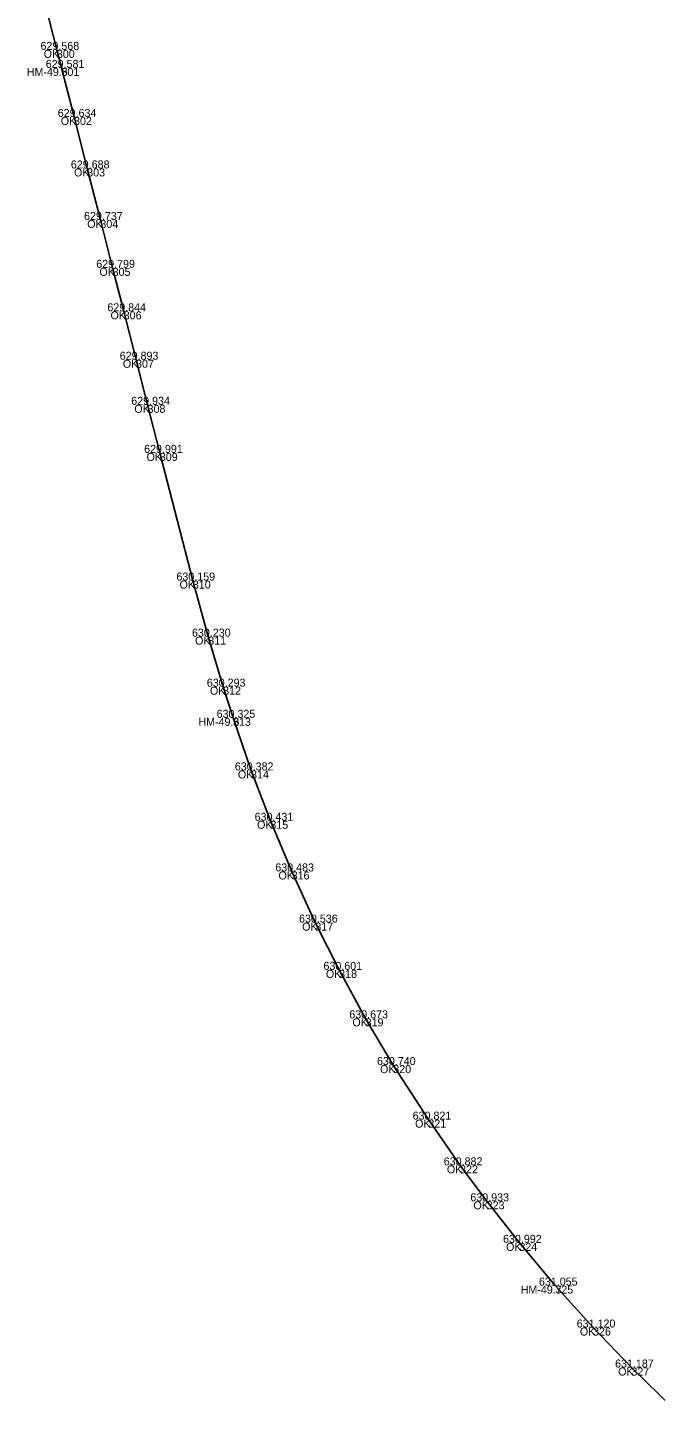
# Model space of a CAD drawing. Extents: x -631472 to -620808, y -1122356 to -1115125.
# Drawn here: x -629565.6 to -629471.4, y -1115712.2 to -1115505.1 of the extents above; entities that cross this region are included whole.
import ezdxf

# ---------------------------------------------------------------- set-up
doc = ezdxf.new("R2010")
doc.units = 0
for name, color, linetype in [('Vrstva 1', 7, 'Continuous'), ('Vrstva 60', 7, 'Continuous'), ('Vrstva 61', 7, 'Continuous'), ('Vrstva 62', 7, 'Continuous')]:
    doc.layers.add(name, color=color, linetype=linetype)

msp = doc.modelspace()

# ---------------------------------------------------------------- linework, layer by layer
at = {"layer": 'Vrstva 1'}
msp.add_lwpolyline([(-629562.87, -1115501.74), (-629561.17, -1115508.42), (-629560.48, -1115511.12), (-629558.59, -1115518.48), (-629556.62, -1115526.2), (-629554.64, -1115533.93), (-629552.8, -1115541.11), (-629551.14, -1115547.63), (-629549.29, -1115554.89), (-629547.56, -1115561.65), (-629545.72, -1115568.86), (-629540.77, -1115588.01), (-629538.45, -1115596.42), (-629536.22, -1115603.92), (-629534.74, -1115608.59), (-629532.03, -1115616.48), (-629529.14, -1115624.03), (-629525.94, -1115631.63), (-629522.39, -1115639.3), (-629518.81, -1115646.39), (-629514.84, -1115653.66), (-629510.69, -1115660.67), (-629505.43, -1115668.85), (-629500.67, -1115675.71), (-629496.68, -1115681.1), (-629491.78, -1115687.33), (-629486.38, -1115693.74), (-629480.72, -1115700.03), (-629474.97, -1115706.03), (-629468.66, -1115712.16)], dxfattribs=at)
at = {"layer": 'Vrstva 60'}
for p, q in [((-629561.17, -1115508.42), (-629561.17, -1115508.42)), ((-629560.48, -1115511.12), (-629560.48, -1115511.12)), ((-629558.59, -1115518.48), (-629558.59, -1115518.48)), ((-629556.62, -1115526.2), (-629556.62, -1115526.2)), ((-629554.64, -1115533.93), (-629554.64, -1115533.93)), ((-629552.8, -1115541.11), (-629552.8, -1115541.11)), ((-629551.14, -1115547.63), (-629551.14, -1115547.63)), ((-629549.29, -1115554.89), (-629549.29, -1115554.89)), ((-629547.56, -1115561.65), (-629547.56, -1115561.65)), ((-629545.72, -1115568.86), (-629545.72, -1115568.86)), ((-629540.77, -1115588.01), (-629540.77, -1115588.01)), ((-629538.45, -1115596.42), (-629538.45, -1115596.42)), ((-629536.22, -1115603.92), (-629536.22, -1115603.92)), ((-629534.74, -1115608.59), (-629534.74, -1115608.59)), ((-629532.03, -1115616.48), (-629532.03, -1115616.48)), ((-629529.14, -1115624.03), (-629529.14, -1115624.03)), ((-629525.94, -1115631.63), (-629525.94, -1115631.63)), ((-629522.39, -1115639.3), (-629522.39, -1115639.3)), ((-629518.81, -1115646.39), (-629518.81, -1115646.39)), ((-629514.84, -1115653.66), (-629514.84, -1115653.66)), ((-629510.69, -1115660.67), (-629510.69, -1115660.67)), ((-629505.43, -1115668.85), (-629505.43, -1115668.85)), ((-629500.67, -1115675.71), (-629500.67, -1115675.71)), ((-629496.68, -1115681.1), (-629496.68, -1115681.1)), ((-629491.78, -1115687.33), (-629491.78, -1115687.33)), ((-629486.38, -1115693.74), (-629486.38, -1115693.74)), ((-629480.72, -1115700.03), (-629480.72, -1115700.03)), ((-629474.97, -1115706.03), (-629474.97, -1115706.03))]:
    msp.add_line(p, q, dxfattribs=at)

# ---------------------------------------------------------------- texts
for s, p in [('300', (-629561.17, -1115509.62)), ('301', (-629560.48, -1115512.32)), ('302', (-629558.59, -1115519.68)), ('303', (-629556.62, -1115527.4)), ('304', (-629554.64, -1115535.13)), ('305', (-629552.8, -1115542.31)), ('306', (-629551.14, -1115548.83)), ('307', (-629549.29, -1115556.09)), ('308', (-629547.56, -1115562.85)), ('309', (-629545.72, -1115570.06)), ('310', (-629540.77, -1115589.21)), ('311', (-629538.45, -1115597.62)), ('312', (-629536.22, -1115605.12)), ('313', (-629534.74, -1115609.79)), ('314', (-629532.03, -1115617.68)), ('315', (-629529.14, -1115625.23)), ('316', (-629525.94, -1115632.83)), ('317', (-629522.39, -1115640.5)), ('318', (-629518.81, -1115647.59)), ('319', (-629514.84, -1115654.86)), ('320', (-629510.69, -1115661.87)), ('321', (-629505.43, -1115670.05)), ('322', (-629500.67, -1115676.91)), ('323', (-629496.68, -1115682.3)), ('324', (-629491.78, -1115688.53)), ('325', (-629486.38, -1115694.94)), ('326', (-629480.72, -1115701.23)), ('327', (-629474.97, -1115707.23))]:
    msp.add_text(s, height=1.2, dxfattribs=at).set_placement(p)
at = {"layer": 'Vrstva 61'}
for s, p in [('629.568', (-629563.62, -1115508.42)), ('629.581', (-629562.84, -1115511.12)), ('629.634', (-629561.04, -1115518.48)), ('629.688', (-629559.07, -1115526.2)), ('629.737', (-629557.09, -1115533.93)), ('629.799', (-629555.26, -1115541.11)), ('629.844', (-629553.59, -1115547.63)), ('629.893', (-629551.74, -1115554.89)), ('629.934', (-629550.01, -1115561.65)), ('629.991', (-629548.08, -1115568.86)), ('630.159', (-629543.23, -1115588.01)), ('630.230', (-629540.9, -1115596.42)), ('630.293', (-629538.67, -1115603.92)), ('630.325', (-629537.2, -1115608.59)), ('630.382', (-629534.47, -1115616.48)), ('630.431', (-629531.5, -1115624.03)), ('630.483', (-629528.39, -1115631.63)), ('630.536', (-629524.84, -1115639.3)), ('630.601', (-629521.17, -1115646.39)), ('630.673', (-629517.29, -1115653.66)), ('630.740', (-629513.14, -1115660.67)), ('630.821', (-629507.79, -1115668.85)), ('630.882', (-629503.12, -1115675.71)), ('630.933', (-629499.13, -1115681.1)), ('630.992', (-629494.23, -1115687.33)), ('631.055', (-629488.84, -1115693.74)), ('631.120', (-629483.17, -1115700.03)), ('631.187', (-629477.42, -1115706.03))]:
    msp.add_text(s, height=1.2, dxfattribs=at).set_placement(p)
at = {"layer": 'Vrstva 62'}
for s, p in [('OK', (-629563.15, -1115509.62)), ('HM-49.5', (-629565.69, -1115512.32)), ('OK', (-629560.58, -1115519.68)), ('OK', (-629558.6, -1115527.4)), ('OK', (-629556.62, -1115535.13)), ('OK', (-629554.79, -1115542.31)), ('OK', (-629553.12, -1115548.83)), ('OK', (-629551.27, -1115556.09)), ('OK', (-629549.55, -1115562.85)), ('OK', (-629547.71, -1115570.06)), ('OK', (-629542.76, -1115589.21)), ('OK', (-629540.43, -1115597.62)), ('OK', (-629538.2, -1115605.12)), ('HM-49.6', (-629539.94, -1115609.79)), ('OK', (-629534.01, -1115617.68)), ('OK', (-629531.13, -1115625.23)), ('OK', (-629527.92, -1115632.83)), ('OK', (-629524.37, -1115640.5)), ('OK', (-629520.8, -1115647.59)), ('OK', (-629516.83, -1115654.86)), ('OK', (-629512.68, -1115661.87)), ('OK', (-629507.42, -1115670.05)), ('OK', (-629502.65, -1115676.91)), ('OK', (-629498.66, -1115682.3)), ('OK', (-629493.77, -1115688.53)), ('HM-49.7', (-629491.58, -1115694.94)), ('OK', (-629482.7, -1115701.23)), ('OK', (-629476.95, -1115707.23))]:
    msp.add_text(s, height=1.2, dxfattribs=at).set_placement(p)

doc.saveas('drawing.dxf')
